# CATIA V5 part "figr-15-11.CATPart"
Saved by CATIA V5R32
Part number: Part1
Bounding box of the stored display mesh (mm): x -50 to 50, y -32.5 to 33.5, z -52 to 1
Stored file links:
  D:\PROJECTS\Project 2022\CATIA V5 6R 2022\Resources\Part Files\c15_catia_v5_6r2022_prt\figr-15-11.CATPart
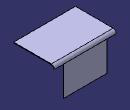
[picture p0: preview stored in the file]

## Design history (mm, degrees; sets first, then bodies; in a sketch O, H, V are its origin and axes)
SheetMetalParameters1: Thickness 1, BendRadius 4, KFactor 0.475772 {= log(min(100,max(20*SheetMetalParameters1.BendRadius,SheetMetalParameters1.Thickness)/SheetMetalParameters1.Thickness))/log(100)/2}, ReliefRadialLength 4, ReliefAxialLength 4, MinimumBendRadius 0
Body1 (main body)
  Sketch1 on xy-plane, origin (0, 0, 0), H (1, 0, 0), V (0, 1, 0)
    line L1 (-50, 32.5) -> (50, 32.5)
    line L2 (50, 32.5) -> (50, -32.5)
    line L3 (50, -32.5) -> (-50, -32.5)
    line L4 (-50, -32.5) -> (-50, 32.5)
    length L1 = 100
    length L2 = 65
    horizontal: L1 H, L3 H
    vertical: L2 V, L4 V
    symmetry: L4 L2 V, L1 L3 H
  Wall1: Thickness 1, Profile Sketch1
  d_NewWallOnEdge1: NewWallOnEdge_Edge edge [face of Wall1 | face of Wall1], NewWallOnEdge_Length 53, NewWallOnEdge_HeightLimitOffset 0, NewWallOnEdge_WidthOffset1 -15, NewWallOnEdge_WidthOffset2 -15, NewWallOnEdge_Angle 90, NewWallOnEdge_BendRadiusValue 4 {= SheetMetalParameters1.BendRadius}, NewWallOnEdge_BendTable SheetMetalParameters1, KFacteur 0.475772 {= log(min(100,max(20*d_NewWallOnEdge1.Radius,SheetMetalParameters1.Thickness)/SheetMetalParameters1.Thickness))/log(100)/2}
